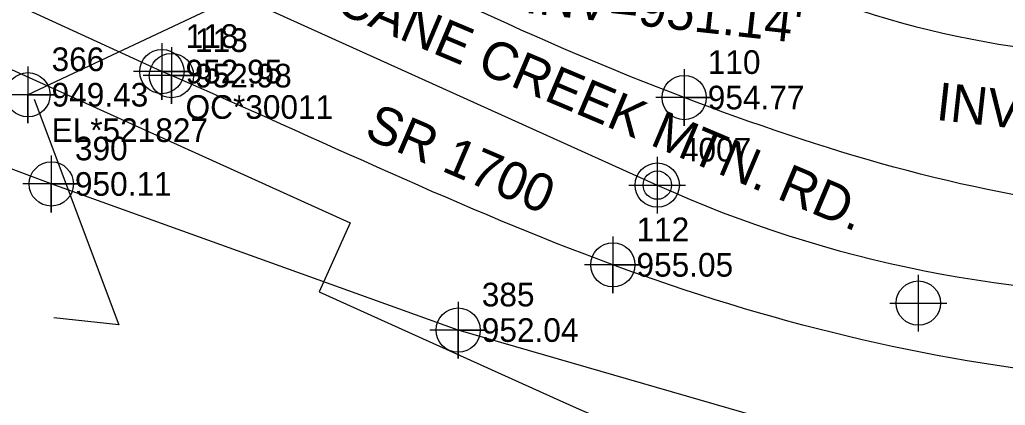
# Model space of a CAD drawing. Extents: x 1150279 to 1151282, y 655434 to 657999.
# Drawn here: x 1150895 to 1150999.3, y 657055.2 to 657096 of the extents above; entities that cross this region are included whole.
import ezdxf

# ---------------------------------------------------------------- set-up
doc = ezdxf.new("R2010")
doc.units = 0
for name, color, linetype in [('COGO Default Chain', 7, 'Continuous'), ('COGO Default Curve', 7, 'Continuous'), ('Cogo Default Point CELL', 7, 'Continuous'), ('COGO Default Point Number', 7, 'Continuous'), ('Exist Horizontal Alignment', 7, 'Continuous'), ('Exist Horizontal Alignment Station Label', 7, 'Continuous'), ('Exist Other Culture Fence Line', 7, 'Continuous'), ('Exist Other Culture Fence Line Cogo Elevation', 7, 'Continuous'), ('Exist Other Culture Fence Line Cogo Number', 7, 'Continuous'), ('Exist Other Culture Fence Line Cogo Point CELL', 7, 'Continuous'), ('Exist Right of Way Line', 7, 'Continuous'), ('Exist Roads EOP', 7, 'Continuous'), ('Exist Roads EOP Cogo Comment', 7, 'Continuous'), ('Exist Roads EOP Cogo Elevation', 7, 'Continuous'), ('Exist Roads EOP Cogo Number', 7, 'Continuous'), ('Exist Roads EOP Cogo Point CELL', 7, 'Continuous'), ('Exist Roads EOP Text', 7, 'Continuous'), ('Exist Structure Minor Pipes CMP 15 Inch Leader', 7, 'Continuous'), ('Exist Structure Minor Pipes CMP 15 Inch Text', 7, 'Continuous'), ('Exist Structure Minor Pipes CMP 18 Inch', 7, 'Continuous'), ('Exist Structure Minor Pipes CMP 18 Inch Cogo Comment', 7, 'Continuous'), ('Exist Structure Minor Pipes CMP 18 Inch Cogo Elevation', 7, 'Continuous'), ('Exist Structure Minor Pipes CMP 18 Inch Cogo Number', 7, 'Continuous'), ('Exist Structure Minor Pipes CMP 18 Inch Cogo Point CELL', 7, 'Continuous')]:
    doc.layers.add(name, color=color, linetype=linetype)

msp = doc.modelspace()

# ---------------------------------------------------------------- linework, layer by layer
at = {"layer": 'COGO Default Chain'}
msp.add_line((1150875.79, 657117.71), (1150962.48, 657078.53), dxfattribs=at)
msp.add_arc((1151016.01, 657196.99), 130, 245.6804, 271.9187, dxfattribs=at)
at = {"layer": 'COGO Default Curve'}
msp.add_arc((1151016.01, 657196.99), 130, 245.6804, 271.9187, dxfattribs=at)
at = {"layer": 'Cogo Default Point CELL'}
for points in [[(1150962.48, 657081.53), (1150962.48, 657078.53)], [(1150962.48, 657081.53), (1150962.48, 657078.53)], [(1150959.48, 657078.53), (1150962.48, 657078.53)], [(1150959.48, 657078.53), (1150962.48, 657078.53)], [(1150962.48, 657078.53), (1150965.48, 657078.53)], [(1150962.48, 657078.53), (1150962.48, 657075.53)], [(1150962.48, 657078.53), (1150965.48, 657078.53)], [(1150962.48, 657078.53), (1150962.48, 657075.53)], [(1150990.09, 657069.05), (1150990.09, 657066.05)], [(1150987.09, 657066.05), (1150990.09, 657066.05)], [(1150990.09, 657066.05), (1150993.09, 657066.05)], [(1150990.09, 657066.05), (1150990.09, 657063.05)]]:
    msp.add_lwpolyline(points, dxfattribs=at)
for centre in [(1150962.48, 657078.53), (1150962.48, 657078.53), (1150990.09, 657066.05)]:
    msp.add_circle(centre, 2.34, dxfattribs=at)
at = {"layer": 'Exist Horizontal Alignment'}
msp.add_line((1150875.79, 657117.71), (1150962.48, 657078.53), dxfattribs=at)
msp.add_arc((1151016.01, 657196.99), 130, 245.6804, 271.9187, dxfattribs=at)
at = {"layer": 'Exist Horizontal Alignment Station Label'}
msp.add_circle((1150962.48, 657078.53), 1.5, dxfattribs=at)
at = {"layer": 'Exist Other Culture Fence Line'}
msp.add_lwpolyline([(1151064.38, 657042.2), (1151035.79, 657039.66), (1150986.53, 657050.15), (1150941.42, 657063.2), (1150898.39, 657078.65), (1150854.86, 657094.99), (1150825.03, 657100.53), (1150812.46, 657091.59), (1150835.17, 657043.74), (1150852.72, 657007.43)], dxfattribs=at)
at = {"layer": 'Exist Other Culture Fence Line Cogo Point CELL'}
for points in [[(1150898.39, 657081.65), (1150898.39, 657075.65), (1150898.39, 657078.65), (1150901.39, 657078.65), (1150895.39, 657078.65)], [(1150941.42, 657066.2), (1150941.42, 657060.2), (1150941.42, 657063.2), (1150944.42, 657063.2), (1150938.42, 657063.2)]]:
    msp.add_lwpolyline(points, dxfattribs=at)
for centre in [(1150898.39, 657078.65), (1150941.42, 657063.2)]:
    msp.add_circle(centre, 2.34, dxfattribs=at)
at = {"layer": 'Exist Right of Way Line'}
for p, q in [((1150868.78, 657102.21), (1150930, 657074.55)), ((1150930, 657074.55), (1150926.71, 657067.26)), ((1150926.71, 657067.26), (1150952.18, 657055.75))]:
    msp.add_line(p, q, dxfattribs=at)
for radius in [105, 155]:
    msp.add_arc((1151016.01, 657196.99), radius, 245.6804, 271.9187, dxfattribs=at)
at = {"layer": 'Exist Roads EOP'}
msp.add_line((1150910.09, 657090.54), (1150866.52, 657110.59), dxfattribs=at)
for points in [[(1151056.23, 657077.09), (1151010.25, 657076.05), (1150965.32, 657087.79), (1150920.52, 657109.03), (1150919.16, 657109.82)], [(1151056.97, 657058.93), (1151008.05, 657058.3), (1150957.78, 657070.1), (1150911.09, 657090.11), (1150910.09, 657090.54)]]:
    msp.add_spline(points, degree=3, dxfattribs=at)
at = {"layer": 'Exist Roads EOP Cogo Point CELL'}
for points in [[(1150910.09, 657093.54), (1150910.09, 657087.54), (1150910.09, 657090.54), (1150913.09, 657090.54), (1150907.09, 657090.54)], [(1150911.09, 657093.11), (1150911.09, 657087.11), (1150911.09, 657090.11), (1150914.09, 657090.11), (1150908.09, 657090.11)], [(1150965.32, 657090.79), (1150965.32, 657084.79), (1150965.32, 657087.79), (1150968.32, 657087.79), (1150962.32, 657087.79)], [(1150957.78, 657073.1), (1150957.78, 657067.1), (1150957.78, 657070.1), (1150960.78, 657070.1), (1150954.78, 657070.1)]]:
    msp.add_lwpolyline(points, dxfattribs=at)
for centre in [(1150910.09, 657090.54), (1150911.09, 657090.11), (1150965.32, 657087.79), (1150957.78, 657070.1)]:
    msp.add_circle(centre, 2.34, dxfattribs=at)
at = {"layer": 'Exist Structure Minor Pipes CMP 15 Inch Leader'}
msp.add_lwpolyline([(1150896.56, 657087.61), (1150905.54, 657063.74), (1150898.67, 657064.5)], dxfattribs=at)
at = {"layer": 'Exist Structure Minor Pipes CMP 18 Inch'}
msp.add_line((1150936.29, 657107.11), (1150895.92, 657088.09), dxfattribs=at)
at = {"layer": 'Exist Structure Minor Pipes CMP 18 Inch Cogo Point CELL'}
msp.add_lwpolyline([(1150895.92, 657091.09), (1150895.92, 657085.09), (1150895.92, 657088.09), (1150898.92, 657088.09), (1150892.92, 657088.09)], dxfattribs=at)
msp.add_circle((1150895.92, 657088.09), 2.34, dxfattribs=at)

# ---------------------------------------------------------------- texts
at = {"layer": 'COGO Default Point Number'}
msp.add_text('4007', height=2.5, dxfattribs=at).set_placement((1150964.98, 657081.03))
at = {"layer": 'Exist Other Culture Fence Line Cogo Elevation'}
for s, p in [('950.11', (1150900.89, 657077.4)), ('952.04', (1150943.92, 657061.95))]:
    msp.add_text(s, height=2.5, dxfattribs=at).set_placement(p)
at = {"layer": 'Exist Other Culture Fence Line Cogo Number'}
for s, p in [('390', (1150900.89, 657081.15)), ('385', (1150943.92, 657065.7))]:
    msp.add_text(s, height=2.5, dxfattribs=at).set_placement(p)
at = {"layer": 'Exist Roads EOP Cogo Comment'}
msp.add_text('OC*30011', height=2.5, dxfattribs=at).set_placement((1150912.59, 657085.54))
at = {"layer": 'Exist Roads EOP Cogo Elevation'}
for s, p in [('952.95', (1150912.59, 657089.29)), ('952.98', (1150913.59, 657088.86)), ('954.77', (1150967.82, 657086.54)), ('955.05', (1150960.28, 657068.85))]:
    msp.add_text(s, height=2.5, dxfattribs=at).set_placement(p)
at = {"layer": 'Exist Roads EOP Cogo Number'}
for s, p in [('118', (1150912.59, 657093.04)), ('113', (1150913.59, 657092.61)), ('110', (1150967.82, 657090.29)), ('112', (1150960.28, 657072.6))]:
    msp.add_text(s, height=2.5, dxfattribs=at).set_placement(p)
at = {"layer": 'Exist Roads EOP Text'}
for s, rotation, p in [('CANE CREEK MTN. RD.', 337.1065, (1150928.18, 657096.94)), ('SR 1700', 336.8099, (1150931.35, 657083.6))]:
    msp.add_text(s, height=4, rotation=rotation, dxfattribs=at).set_placement(p)
at = {"layer": 'Exist Structure Minor Pipes CMP 15 Inch Text'}
for s, p in [("INV=951.14'", (1150948.37, 657096.77)), ("INV=957.10'", (1150991.87, 657085.44))]:
    msp.add_text(s, height=4, rotation=353.6867, dxfattribs=at).set_placement(p)
at = {"layer": 'Exist Structure Minor Pipes CMP 18 Inch Cogo Comment'}
msp.add_text('EL*521827', height=2.5, dxfattribs=at).set_placement((1150898.42, 657083.09))
at = {"layer": 'Exist Structure Minor Pipes CMP 18 Inch Cogo Elevation'}
msp.add_text('949.43', height=2.5, dxfattribs=at).set_placement((1150898.42, 657086.84))
at = {"layer": 'Exist Structure Minor Pipes CMP 18 Inch Cogo Number'}
msp.add_text('366', height=2.5, dxfattribs=at).set_placement((1150898.42, 657090.59))

doc.saveas('drawing.dxf')
